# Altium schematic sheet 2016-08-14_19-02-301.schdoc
size 364 x 128 mm; SheetNumber: 1; SheetTotal: 1
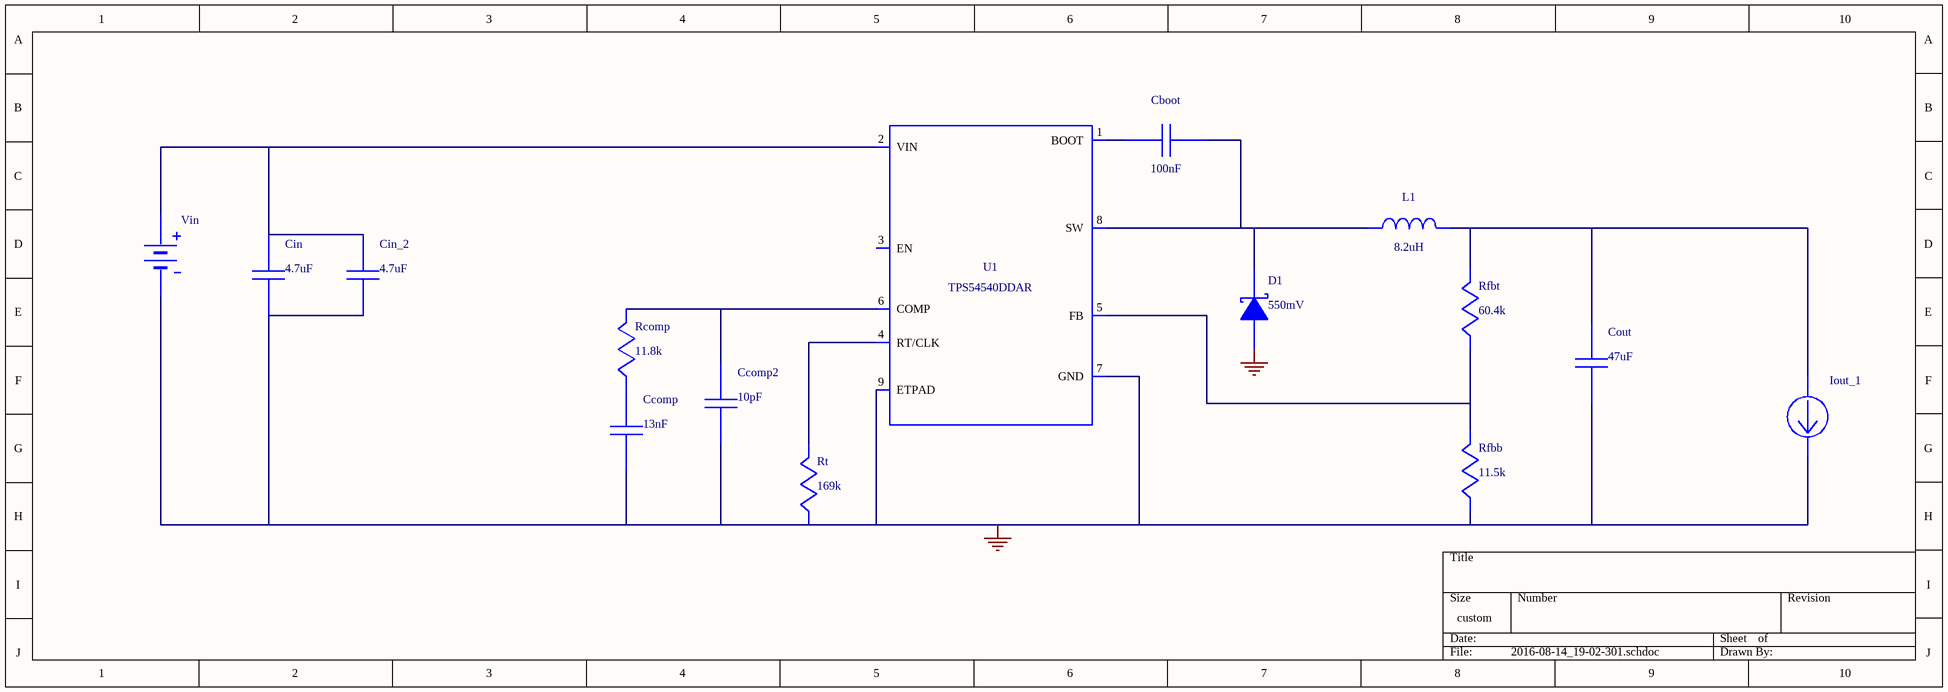
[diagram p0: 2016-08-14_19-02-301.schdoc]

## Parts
Cboot  value 100nF  (hidden comment: GRM155R61A104KA01D)
Ccomp  value 13nF  (hidden comment: GRM3195C1H133JA01D)
Ccomp2  value 10pF  (hidden comment: C0805C100K5GACTU)
Cin  value 4.7uF  (hidden comment: GRM31CR71H475KA12L)
Cin_2  value 4.7uF  (hidden comment: GRM31CR71H475KA12L)
Cout  value 47uF  (hidden comment: GRM32ER61A476KE20L)
D1  value 550mV  (hidden comment: B540C-13-F)
Iout_1  WB_CURRENT_LOAD  (value not drawn)
L1  value 8.2uH  (hidden comment: SRP6540-8R2M)
Rcomp  value 11.8k  (hidden comment: CRCW040211K8FKED)
Rfbb  value 11.5k  (hidden comment: CRCW040211K5FKED)
Rfbt  value 60.4k  (hidden comment: CRCW040260K4FKED)
Rt  value 169k  (hidden comment: CRCW0402169KFKED)
U1  TPS54540DDAR
Vin  WB_BATTERY  (value not drawn)

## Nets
0: Ccomp.2 Ccomp2.2 Cin.2 Cin_2.2 Cout.2 D1.2(A) Iout_1.2(-) Rfbb.2 Rt.2 U1.7(GND) U1.9(ETPAD) Vin.2(-)
NetCboot_1: Cboot.1 U1.1(BOOT)
NetCboot_2: Cboot.2 D1.1(K) L1.1 U1.8(SW)
NetCcomp2_1: Ccomp2.1 Rcomp.1 U1.6(COMP)
NetCcomp_1: Ccomp.1 Rcomp.2
NetCin_1: Cin.1 Cin_2.1 U1.2(VIN) Vin.1(+)
NetCout_1: Cout.1 Iout_1.1(+) L1.2 Rfbt.1
NetRfbb_1: Rfbb.1 Rfbt.2 U1.5(FB)
NetRt_1: Rt.1 U1.4(RT/CLK)

Not connected (* = marked no-connect by the designer): U1 3(EN)

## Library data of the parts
Cboot = GRM155R61A104KA01D: GRM155R61A104KA0; Manufacturer Name: MuRata
Ccomp = GRM3195C1H133JA01D: GRM3195C1H133JA0; Manufacturer Name: MuRata
Ccomp2 = C0805C100K5GACTU: Manufacturer Name: Kemet
Cin Cin_2 = GRM31CR71H475KA12L: GRM31CR71H475KA1; Manufacturer Name: MuRata
Cout = GRM32ER61A476KE20L: GRM32ER61A476KE2; Manufacturer Name: MuRata
D1 = B540C-13-F: Manufacturer Name: Diodes Inc.
L1 = SRP6540-8R2M: Unknown; Manufacturer Name: Bourns
Rcomp = CRCW040211K8FKED: Manufacturer Name: Vishay-Dale
Rfbb = CRCW040211K5FKED: Manufacturer Name: Vishay-Dale
Rfbt = CRCW040260K4FKED: Manufacturer Name: Vishay-Dale
Rt = CRCW0402169KFKED: Manufacturer Name: Vishay-Dale
U1 = TPS54540DDAR: Manufacturer Name: Texas Instruments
